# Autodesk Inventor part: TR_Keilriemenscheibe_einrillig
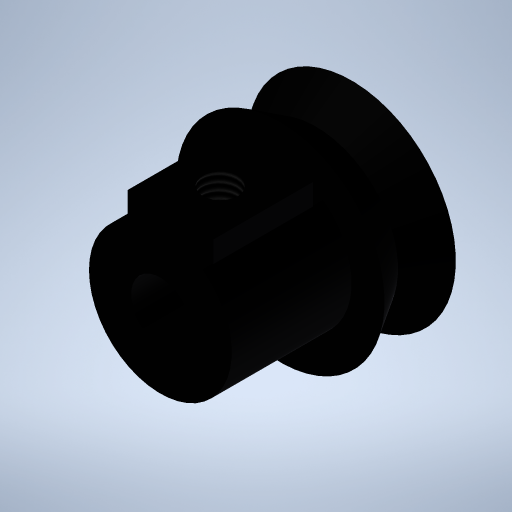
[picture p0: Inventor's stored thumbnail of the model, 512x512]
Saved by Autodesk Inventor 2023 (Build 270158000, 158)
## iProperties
Created: 2023-11
Part Number: TR_Keilriemenscheibe_einrillig
Material: PC/ABS-Kunststoff
Document SubType Name: Modeling
Designer: Admin
Density: 0.357273 g/cm^3
Appearance: Glatt - Schwarz
Author: Admin
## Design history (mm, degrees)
sketch "Skizze1"
  geometry: L1 (0, 0)-(5, 0); L2 (5, 0)-(5, -8.4); L3 (5, -8.4)-(7.3, -8.4); L4 (7.3, -8.4)-(5.75, -10.9); L5 (5.75, -10.9)-(7.3, -13.4); L6 (7.3, -13.4)-(0, -13.4); L7 (0, -13.4)-(0, 0)
  constraints: 14 end point, 2 perpendicular, 1 equal length, 1 horizontal, 1 parallel, 1 vertical, 1 vertical alignment
  dimensions: "d0" = 5 distance of L1.start L1.end (= 0.5 x Einheitsmaß); "d1" = 8.4 distance of L1.end L2.end; "d2" = 7.3 distance of L5.end L6.end; "d3" = 5 distance of L5.end L3.end; "d4" = 5.75 horizontal distance of L1.start L4.end
revolve "Umdrehung1" sketch "Skizze1" stored, may be unused: angle "d5" = 90 deg
sketch "Skizze2"
  geometry: L1 (3, -0.7)-(-3, -0.7); L2 (-3, -0.7)-(-3, -7.7); L3 (-3, -7.7)-(3, -7.7); L4 (3, -7.7)-(3, -0.7); L5 (5, -8.4)-(5, 0) reference; 4 further points
  constraints: 8 end point, 3 midpoint, 2 parallel, 1 horizontal, 1 horizontal alignment, 1 perpendicular, 1 vertical alignment
  dimensions: "d6" = 7 distance of L3.end L1.start; "d7" = 6 distance of L1.start L1.end
extrude "Extrusion1" join sketch "Skizze2" distance "d8" = 5.5; taper "d9" = 0 deg
sketch "Skizze3"
  geometry: L1 (-3, 7.7)-(-3, 0.7) reference; 3 further points
  constraints: 1 horizontal alignment, 1 midpoint, 1 vertical alignment
hole "Bohrung1" sketch "Skizze3" at (0, 4.2) diameter "d10" = 2.459; stored, may be unused: countersink angle "d14" = 90 deg, drill point angle "d16" = 0 deg; dims "d11" = 5, "d12" = 4, "d13" = 2, "d15" = 5
sketch "Skizze4"
  geometry: C1 r 2.05 at (0, 0); 1 further point
  constraints: 1 centre point, 1 coincident
  dimensions: "d17" = 4.1 diameter of C1 (= DAchsAufnahme)
extrude "Extrusion2" cut sketch "Skizze4" extent not by distance; stored distance "d18" = 0; taper "d19" = 0 deg
node "Volumenkörper1"
other parameters: "Radius" = 2.075 [user parameter], "Fasen" = 0.5 [user parameter], "Dicke" = 0.8 [user parameter], "Breitloch" = 2 [user parameter], "Langloch" = 32 [user parameter], "AchteckUmkreis" = 6 [user parameter], "DAchsAufnahme" = 4.1 [user parameter; used in 1 equation term]
